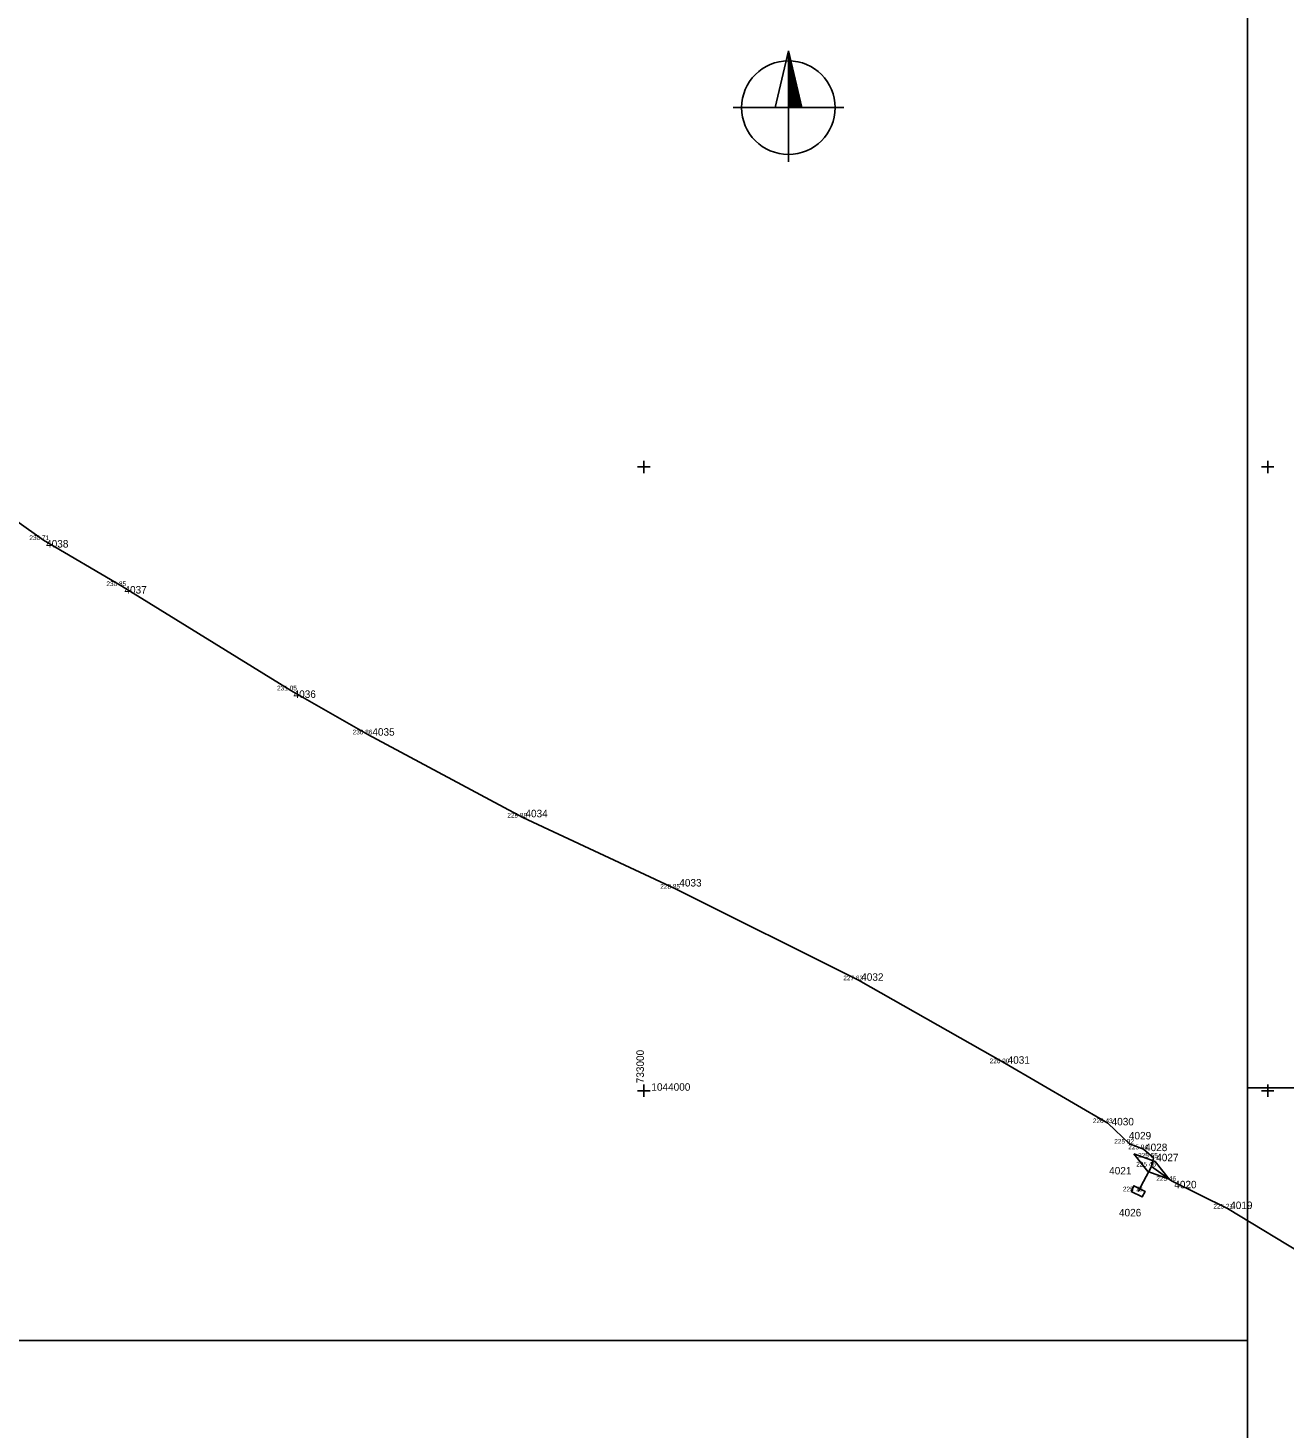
# Model space of a CAD drawing. Extents: x -736532 to -730799, y -1045301 to -1042399.
# Drawn here: x -733098.7 to -732897.2, y -1044054.1 to -1043829.6 of the extents above; entities that cross this region are included whole.
import ezdxf

# ---------------------------------------------------------------- set-up
doc = ezdxf.new("R2010")
doc.units = 0
for name, color, linetype in [('Vrstva 25', 7, 'Continuous'), ('Vrstva 26', 7, 'Continuous'), ('Vrstva 50', 7, 'Continuous'), ('Vrstva 60', 7, 'Continuous'), ('Vrstva 61', 7, 'Continuous'), ('Vrstva 62', 7, 'Continuous'), ('Vrstva 63', 7, 'Continuous')]:
    doc.layers.add(name, color=color, linetype=linetype)

msp = doc.modelspace()

# ---------------------------------------------------------------- linework, layer by layer
at = {"layer": 'Vrstva 25'}
msp.add_lwpolyline([(-732921.9, -1044016.13), (-732921.46, -1044015.23), (-732919.67, -1044016.13), (-732920.11, -1044017.02), (-732921.9, -1044016.13)], dxfattribs=at)
at = {"layer": 'Vrstva 26'}
for points in [[(-732893.05, -1044027.01), (-732906.46, -1044018.88), (-732915.42, -1044014.44), (-732918.63, -1044012.15), (-732918.32, -1044010.73), (-732919.9, -1044009.39), (-732922.14, -1044008.49), (-732925.61, -1044005.19), (-732942.14, -1043995.59), (-732965.61, -1043982.3), (-732994.91, -1043967.61), (-733019.43, -1043956.22), (-733044.25, -1043942.87), (-733056.6, -1043935.82), (-733083.71, -1043919.1), (-733096.27, -1043911.72), (-733104.86, -1043905.67), (-733118.71, -1043897.93), (-733134.71, -1043889.66), (-733155.34, -1043880.34), (-733176.55, -1043869.7), (-733189.82, -1043860.6), (-733221.68, -1043837.28), (-733239.17, -1043824.75)], [(-732921.48, -1044010.12), (-732918.05, -1044011.33), (-732915.78, -1044014.18), (-732919.21, -1044012.96), (-732921.48, -1044010.12)], [(-732918.63, -1044012.15), (-732920.79, -1044016.13)]]:
    msp.add_lwpolyline(points, dxfattribs=at)
at = {"layer": 'Vrstva 50'}
for p, q in [((-732976.83, -1043833.3), (-732978.96, -1043842.4)), ((-732974.7, -1043842.4), (-732976.83, -1043833.3)), ((-732976.83, -1043833.3), (-732976.83, -1043851.11)), ((-732976.83, -1043833.65), (-732976.75, -1043833.65)), ((-732976.83, -1043833.78), (-732976.72, -1043833.78)), ((-732976.83, -1043833.9), (-732976.69, -1043833.9)), ((-732976.83, -1043834.03), (-732976.66, -1043834.03)), ((-732976.83, -1043834.15), (-732976.63, -1043834.15)), ((-732976.83, -1043834.28), (-732976.6, -1043834.28)), ((-732976.83, -1043834.4), (-732976.57, -1043834.4)), ((-732976.83, -1043834.53), (-732976.55, -1043834.53)), ((-732976.83, -1043834.65), (-732976.52, -1043834.65)), ((-732976.83, -1043834.78), (-732976.49, -1043834.78)), ((-732976.83, -1043834.9), (-732976.46, -1043834.9)), ((-732976.83, -1043835.03), (-732976.43, -1043835.03)), ((-732976.83, -1043835.15), (-732976.4, -1043835.15)), ((-732976.83, -1043835.28), (-732976.37, -1043835.28)), ((-732976.83, -1043835.4), (-732976.34, -1043835.4)), ((-732976.83, -1043835.53), (-732976.31, -1043835.53)), ((-732976.83, -1043835.65), (-732976.28, -1043835.65)), ((-732976.83, -1043835.78), (-732976.25, -1043835.78)), ((-732976.83, -1043835.9), (-732976.22, -1043835.9)), ((-732976.83, -1043836.03), (-732976.19, -1043836.03)), ((-732976.83, -1043836.15), (-732976.17, -1043836.15)), ((-732976.83, -1043836.28), (-732976.14, -1043836.28)), ((-732976.83, -1043836.4), (-732976.11, -1043836.4)), ((-732976.83, -1043836.53), (-732976.08, -1043836.53)), ((-732976.83, -1043836.65), (-732976.05, -1043836.65)), ((-732976.83, -1043836.78), (-732976.02, -1043836.78)), ((-732976.83, -1043836.9), (-732975.99, -1043836.9)), ((-732976.83, -1043837.03), (-732975.96, -1043837.03)), ((-732976.83, -1043837.15), (-732975.93, -1043837.15)), ((-732976.83, -1043837.28), (-732975.9, -1043837.28)), ((-732976.83, -1043837.4), (-732975.87, -1043837.4)), ((-732976.83, -1043837.53), (-732975.84, -1043837.53)), ((-732976.83, -1043837.65), (-732975.81, -1043837.65)), ((-732976.83, -1043837.78), (-732975.79, -1043837.78)), ((-732976.83, -1043837.9), (-732975.76, -1043837.9)), ((-732976.83, -1043838.03), (-732975.73, -1043838.03)), ((-732976.83, -1043838.15), (-732975.7, -1043838.15)), ((-732976.83, -1043838.28), (-732975.67, -1043838.28)), ((-732976.83, -1043838.4), (-732975.64, -1043838.4)), ((-732976.83, -1043838.53), (-732975.61, -1043838.53)), ((-732976.83, -1043838.65), (-732975.58, -1043838.65)), ((-732976.83, -1043838.78), (-732975.55, -1043838.78)), ((-732976.83, -1043838.9), (-732975.52, -1043838.9)), ((-732976.83, -1043839.03), (-732975.49, -1043839.03)), ((-732976.83, -1043839.15), (-732975.46, -1043839.15)), ((-732976.83, -1043839.28), (-732975.44, -1043839.28)), ((-732976.83, -1043839.4), (-732975.41, -1043839.4)), ((-732976.83, -1043839.53), (-732975.38, -1043839.53)), ((-732976.83, -1043839.65), (-732975.35, -1043839.65)), ((-732976.83, -1043839.78), (-732975.32, -1043839.78)), ((-732976.83, -1043839.9), (-732975.29, -1043839.9)), ((-732976.83, -1043840.03), (-732975.26, -1043840.03)), ((-732976.83, -1043840.15), (-732975.23, -1043840.15)), ((-732985.71, -1043842.4), (-732967.95, -1043842.4)), ((-732976.83, -1043840.28), (-732975.2, -1043840.28)), ((-732976.83, -1043840.4), (-732975.17, -1043840.4)), ((-732976.83, -1043840.53), (-732975.14, -1043840.53)), ((-732976.83, -1043840.65), (-732975.11, -1043840.65)), ((-732976.83, -1043840.78), (-732975.08, -1043840.78)), ((-732976.83, -1043840.9), (-732975.06, -1043840.9)), ((-732976.83, -1043841.03), (-732975.03, -1043841.03)), ((-732976.83, -1043841.15), (-732975, -1043841.15)), ((-732976.83, -1043841.28), (-732974.97, -1043841.28)), ((-732976.83, -1043841.4), (-732974.94, -1043841.4)), ((-732976.83, -1043841.53), (-732974.91, -1043841.53)), ((-732976.83, -1043841.65), (-732974.88, -1043841.65)), ((-732976.83, -1043841.78), (-732974.85, -1043841.78)), ((-732976.83, -1043841.9), (-732974.82, -1043841.9)), ((-732976.83, -1043842.03), (-732974.79, -1043842.03)), ((-732976.83, -1043842.15), (-732974.76, -1043842.15)), ((-732976.83, -1043842.28), (-732974.73, -1043842.28))]:
    msp.add_line(p, q, dxfattribs=at)
msp.add_circle((-732976.83, -1043842.4), 7.5, dxfattribs=at)
at = {"layer": 'Vrstva 60'}
for p, q in [((-733096.27, -1043911.72), (-733096.27, -1043911.72)), ((-733083.71, -1043919.1), (-733083.71, -1043919.1)), ((-733056.6, -1043935.82), (-733056.6, -1043935.82)), ((-733044.25, -1043942.87), (-733044.25, -1043942.87)), ((-733019.43, -1043956.22), (-733019.43, -1043956.22)), ((-732994.91, -1043967.61), (-732994.91, -1043967.61)), ((-732965.61, -1043982.3), (-732965.61, -1043982.3)), ((-732942.14, -1043995.59), (-732942.14, -1043995.59)), ((-732925.61, -1044005.19), (-732925.61, -1044005.19)), ((-732922.14, -1044008.49), (-732922.14, -1044008.49)), ((-732919.9, -1044009.39), (-732919.9, -1044009.39)), ((-732918.63, -1044012.15), (-732918.63, -1044012.15)), ((-732918.32, -1044010.73), (-732918.32, -1044010.73)), ((-732915.42, -1044014.44), (-732915.42, -1044014.44)), ((-732920.79, -1044016.13), (-732920.79, -1044016.13)), ((-732906.46, -1044018.88), (-732906.46, -1044018.88))]:
    msp.add_line(p, q, dxfattribs=at)
at = {"layer": 'Vrstva 61'}
for p, q in [((-733001, -1043900), (-732999, -1043900)), ((-733000, -1043899), (-733000, -1043901)), ((-732901, -1043900), (-732899, -1043900)), ((-732900, -1043899), (-732900, -1043901)), ((-733000, -1043999), (-733000, -1044001)), ((-732900, -1043999), (-732900, -1044001)), ((-733001, -1044000), (-732999, -1044000)), ((-732901, -1044000), (-732899, -1044000))]:
    msp.add_line(p, q, dxfattribs=at)
at = {"layer": 'Vrstva 63'}
for points in [[(-733307.36, -1043761.08), (-732903.24, -1043761.08), (-732903.24, -1044040.04), (-733307.36, -1044040.04)], [(-732903.24, -1043999.54), (-732499.11, -1043999.54), (-732499.11, -1044278.5), (-732903.24, -1044278.5)]]:
    msp.add_lwpolyline(points, close=True, dxfattribs=at)

# ---------------------------------------------------------------- texts
at = {"layer": 'Vrstva 61'}
for s, p in [(' 4038', (-733096.27, -1043912.92)), (' 4037', (-733083.71, -1043920.3)), (' 4036', (-733056.6, -1043937.02)), (' 4035', (-733043.97, -1043943.08)), (' 4034', (-733019.43, -1043956.16)), (' 4033', (-732994.77, -1043967.26)), (' 4032', (-732965.61, -1043982.37)), (' 4031', (-732942.14, -1043995.67)), (' 4030', (-732925.47, -1044005.55)), (' 4029', (-732922.7, -1044007.8)), (' 4028', (-732920.11, -1044009.68)), (' 4027', (-732918.32, -1044011.3)), (' 4021', (-732925.86, -1044013.42)), (' 4020', (-732915.42, -1044015.64)), (' 4026', (-732924.29, -1044020.14)), (' 4019', (-732906.46, -1044018.96))]:
    msp.add_text(s, height=1.2, dxfattribs=at).set_placement(p)
at = {"layer": 'Vrstva 62'}
for s, p in [('230 71 ', (-733098.51, -1043911.72)), ('230 85 ', (-733086.16, -1043919.1)), ('231 05 ', (-733058.8, -1043935.82)), ('230 86 ', (-733046.69, -1043942.87)), ('229 88 ', (-733021.89, -1043956.22)), ('228 85 ', (-732997.37, -1043967.61)), ('227 63 ', (-732968.04, -1043982.3)), ('226 90 ', (-732944.58, -1043995.59)), ('226 43 ', (-732928.03, -1044005.19)), ('225 92 ', (-732924.6, -1044008.49)), ('225 94 ', (-732922.36, -1044009.39)), ('225 55 ', (-732920.78, -1044010.73)), ('225 46 ', (-732921.08, -1044012.15)), ('225 46 ', (-732917.86, -1044014.44)), ('225 73 ', (-732923.22, -1044016.13)), ('225 21 ', (-732908.71, -1044018.88))]:
    msp.add_text(s, height=0.75, dxfattribs=at).set_placement(p)
at = {"layer": 'Vrstva 63'}
msp.add_text('733000', height=1.2, rotation=90, dxfattribs=at).set_placement((-733000, -1043998.8))
msp.add_text('1044000', height=1.2, dxfattribs=at).set_placement((-732998.8, -1044000))

doc.saveas('drawing.dxf')
